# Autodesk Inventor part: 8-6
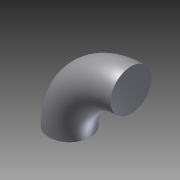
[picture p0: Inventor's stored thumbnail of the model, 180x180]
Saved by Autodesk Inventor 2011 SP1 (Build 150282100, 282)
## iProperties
Created: 2014-01
Part Number: 8-6
Document SubType Name: Modeling
Designer: Administrator
Density: 1 g/cm^3
Author: Administrator
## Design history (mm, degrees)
sketch "草图1"
  geometry: L1 (54, 19.867)-(54, -21.673); C1 r 18 at (0, 0); 1 further point
  constraints: 2 end point, 1 centre point, 1 coincident, 1 vertical
  dimensions: "d0" = 36 diameter of C1; "d1" = 54 distance from line of L1 C1.centre
revolve "旋转1" sketch "草图1" stored, may be unused: angle "d2" = 90 deg
node "实体1"
